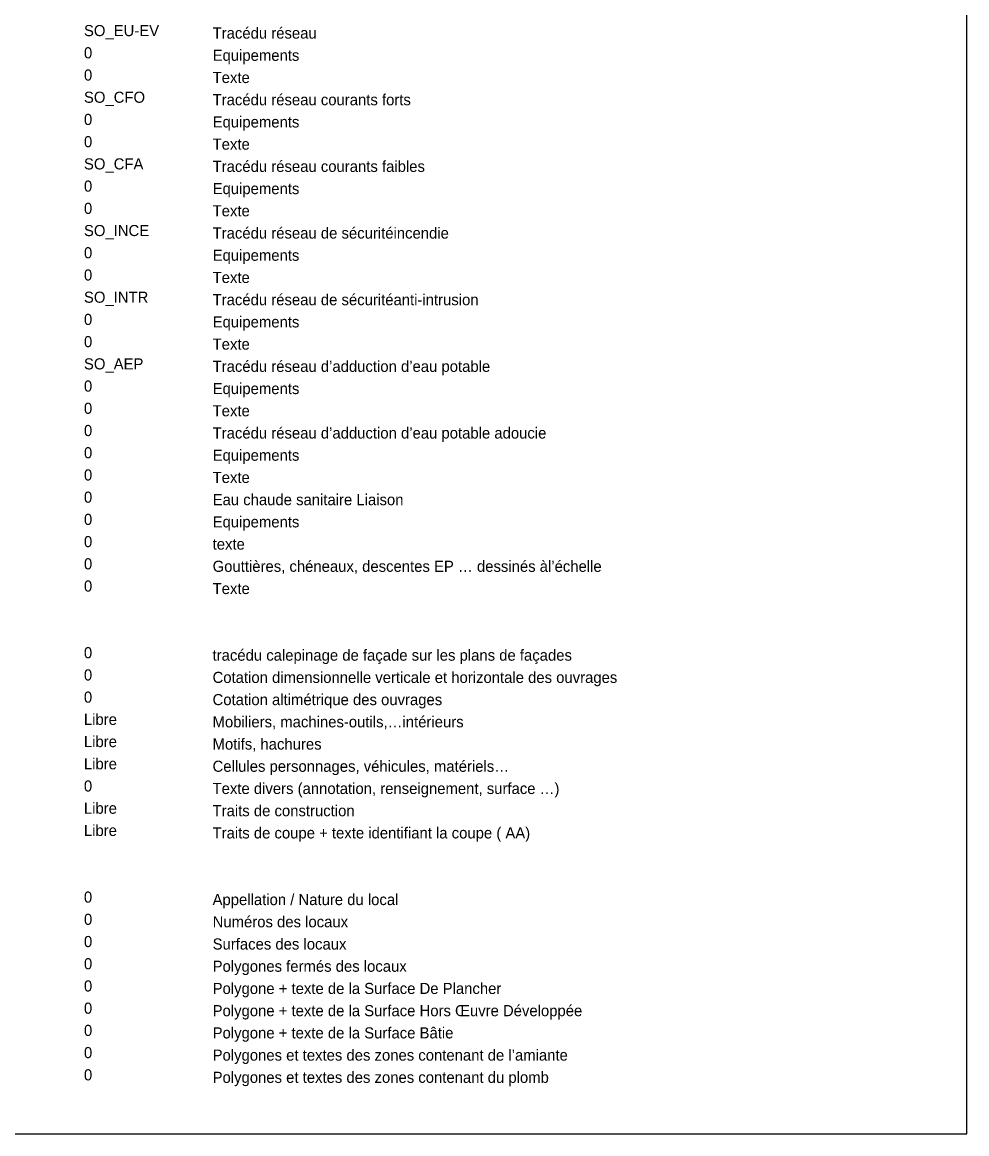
# Model space of a CAD drawing. Extents: x -60 to 214, y -380 to -21.
# Drawn here: x 166.2 to 208.7, y -120.9 to -70.9 of the extents above; entities that cross this region are included whole.
import ezdxf

# ---------------------------------------------------------------- set-up
doc = ezdxf.new("R2010")
doc.units = 0
for name, color, linetype in [('BAT_DH_CALEPINAGE_FACADE', 7, 'Continuous'), ('BAT_DH_COTATION', 7, 'Continuous'), ('BAT_DH_COTATION_NGF', 7, 'Continuous'), ('BAT_DH_EQUIP INTERIEUR', 7, 'Continuous'), ('BAT_DH_HACHURE-MOTIF', 7, 'Continuous'), ('BAT_DH_PERSONNAGE_VEHICULES', 7, 'Continuous'), ('BAT_DH_TEXTE', 7, 'Continuous'), ('BAT_DH_TRAIT CONSTRUCTION', 7, 'Continuous'), ('BAT_DH_TRAIT DE COUPE', 7, 'Continuous'), ('BAT_SID_AMIANTE_POLYLIGNE_TEXTE', 7, 'Continuous'), ('BAT_SID_LOCAL_NOM', 7, 'Continuous'), ('BAT_SID_LOCAL_NUMERO', 7, 'Continuous'), ('BAT_SID_LOCAL_POLYLIGNE', 7, 'Continuous'), ('BAT_SID_LOCAL_SURFACE', 7, 'Continuous'), ('BAT_SID_PLOMB_POLYLIGNE_TEXTE', 7, 'Continuous'), ('BAT_SID_SBAT_POLYLIGNE_TEXTE', 7, 'Continuous'), ('BAT_SID_SDP_POLYLIGNE_TEXTE', 7, 'Continuous'), ('BAT_SID_SHOD_POLYLIGNE_TEXTE', 7, 'Continuous'), ('Default', 7, 'Continuous'), ('SO_AEP_AD_EQUIP', 7, 'Continuous'), ('SO_AEP_AD_LIAISON', 7, 'Continuous'), ('SO_AEP_AD_TEXTE', 7, 'Continuous'), ('SO_AEP_EQUIP', 7, 'Continuous'), ('SO_AEP_LIAISON', 7, 'Continuous'), ('SO_AEP_TEXTE', 7, 'Continuous'), ('SO_ANTI_INTRUSION_EQUIP', 7, 'Continuous'), ('SO_ANTI_INTRUSION_LIAISON', 7, 'Continuous'), ('SO_ANTI_INTRUSION_TEXTE', 7, 'Continuous'), ('SO_ECS_EQUIP', 7, 'Continuous'), ('SO_ECS_LIAISON', 7, 'Continuous'), ('SO_ECS_TEXTE', 7, 'Continuous'), ('SO_ELEC_C_FAIBLES_EQUIP', 7, 'Continuous'), ('SO_ELEC_C_FAIBLES_LIAISON', 7, 'Continuous'), ('SO_ELEC_C_FAIBLES_TEXTE', 7, 'Continuous'), ('SO_ELEC_C_FORTS_EQUIP', 7, 'Continuous'), ('SO_ELEC_C_FORTS_LIAISON', 7, 'Continuous'), ('SO_ELEC_C_FORTS_TEXTE', 7, 'Continuous'), ('SO_EP_EQUIP', 7, 'Continuous'), ('SO_EP_TEXTE', 7, 'Continuous'), ('SO_EU_EV_EQUIP', 7, 'Continuous'), ('SO_EU_EV_LIAISON', 7, 'Continuous'), ('SO_EU_EV_TEXTE', 7, 'Continuous'), ('SO_SECU_INCENDIE_EQUIP', 7, 'Continuous'), ('SO_SECU_INCENDIE_LIAISON', 7, 'Continuous'), ('SO_SECU_INCENDIE_TEXTE', 7, 'Continuous')]:
    doc.layers.add(name, color=color, linetype=linetype)

msp = doc.modelspace()

# ---------------------------------------------------------------- linework, layer by layer
at = {"layer": 'Default'}
msp.add_lwpolyline([(208.701, -25.727), (123.7, -25.727), (123.7, -120.902), (208.701, -120.902)], close=True, dxfattribs=at)

# ---------------------------------------------------------------- texts
at = {"layer": 'BAT_DH_CALEPINAGE_FACADE'}
for s, p in [('0 ', (168.976, -99.499)), ('tracédu calepinage de façade sur les plans de façades ', (174.765, -99.61))]:
    msp.add_text(s, height=0.5, dxfattribs=at).set_placement(p)
at = {"layer": 'BAT_DH_COTATION'}
for s, p in [('0 ', (168.976, -100.499)), ('Cotation dimensionnelle verticale et horizontale des ouvrages ', (174.765, -100.61))]:
    msp.add_text(s, height=0.5, dxfattribs=at).set_placement(p)
at = {"layer": 'BAT_DH_COTATION_NGF'}
for s, p in [('0 ', (168.976, -101.499)), ('Cotation altimétrique des ouvrages ', (174.765, -101.61))]:
    msp.add_text(s, height=0.5, dxfattribs=at).set_placement(p)
at = {"layer": 'BAT_DH_EQUIP INTERIEUR'}
for s, p in [('Libre ', (168.976, -102.499)), ('Mobiliers, machines-outils,…intérieurs ', (174.765, -102.61))]:
    msp.add_text(s, height=0.5, dxfattribs=at).set_placement(p)
at = {"layer": 'BAT_DH_HACHURE-MOTIF'}
for s, p in [('Libre ', (168.976, -103.499)), ('Motifs, hachures ', (174.765, -103.61))]:
    msp.add_text(s, height=0.5, dxfattribs=at).set_placement(p)
at = {"layer": 'BAT_DH_PERSONNAGE_VEHICULES'}
for s, p in [('Libre ', (168.976, -104.499)), ('Cellules personnages, véhicules, matériels…', (174.765, -104.61))]:
    msp.add_text(s, height=0.5, dxfattribs=at).set_placement(p)
at = {"layer": 'BAT_DH_TEXTE'}
for s, p in [('0 ', (168.976, -105.499)), ('Texte divers (annotation, renseignement, surface …)  ', (174.765, -105.61))]:
    msp.add_text(s, height=0.5, dxfattribs=at).set_placement(p)
at = {"layer": 'BAT_DH_TRAIT CONSTRUCTION'}
for s, p in [('Libre ', (168.976, -106.499)), ('Traits de construction  ', (174.765, -106.61))]:
    msp.add_text(s, height=0.5, dxfattribs=at).set_placement(p)
at = {"layer": 'BAT_DH_TRAIT DE COUPE'}
for s, p in [('Libre ', (168.976, -107.499)), ('Traits de coupe + texte identifiant la coupe ( AA) ', (174.765, -107.61))]:
    msp.add_text(s, height=0.5, dxfattribs=at).set_placement(p)
at = {"layer": 'BAT_SID_AMIANTE_POLYLIGNE_TEXTE'}
for s, p in [('0 ', (168.978, -117.499)), ('Polygones et textes des zones contenant de l’amiante ', (174.768, -117.61))]:
    msp.add_text(s, height=0.5, dxfattribs=at).set_placement(p)
at = {"layer": 'BAT_SID_LOCAL_NOM'}
for s, p in [('0 ', (168.976, -110.499)), ('Appellation / Nature du local ', (174.765, -110.61))]:
    msp.add_text(s, height=0.5, dxfattribs=at).set_placement(p)
at = {"layer": 'BAT_SID_LOCAL_NUMERO'}
for s, p in [('0 ', (168.978, -111.499)), ('Numéros des locaux ', (174.768, -111.61))]:
    msp.add_text(s, height=0.5, dxfattribs=at).set_placement(p)
at = {"layer": 'BAT_SID_LOCAL_POLYLIGNE'}
for s, p in [('0 ', (168.978, -113.499)), ('Polygones fermés des locaux ', (174.768, -113.61))]:
    msp.add_text(s, height=0.5, dxfattribs=at).set_placement(p)
at = {"layer": 'BAT_SID_LOCAL_SURFACE'}
for s, p in [('0 ', (168.978, -112.499)), ('Surfaces des locaux ', (174.768, -112.61))]:
    msp.add_text(s, height=0.5, dxfattribs=at).set_placement(p)
at = {"layer": 'BAT_SID_PLOMB_POLYLIGNE_TEXTE'}
for s, p in [('0 ', (168.978, -118.499)), ('Polygones et textes des zones contenant du plomb ', (174.768, -118.61))]:
    msp.add_text(s, height=0.5, dxfattribs=at).set_placement(p)
at = {"layer": 'BAT_SID_SBAT_POLYLIGNE_TEXTE'}
for s, p in [('0 ', (168.978, -116.499)), ('Polygone + texte de la Surface Bâtie ', (174.768, -116.61))]:
    msp.add_text(s, height=0.5, dxfattribs=at).set_placement(p)
at = {"layer": 'BAT_SID_SDP_POLYLIGNE_TEXTE'}
for s, p in [('0 ', (168.978, -114.499)), ('Polygone + texte de la Surface De Plancher ', (174.768, -114.61))]:
    msp.add_text(s, height=0.5, dxfattribs=at).set_placement(p)
at = {"layer": 'BAT_SID_SHOD_POLYLIGNE_TEXTE'}
for s, p in [('0 ', (168.978, -115.499)), ('Polygone + texte de la Surface Hors Œuvre Développée ', (174.768, -115.61))]:
    msp.add_text(s, height=0.5, dxfattribs=at).set_placement(p)
at = {"layer": 'SO_AEP_AD_EQUIP'}
for s, p in [('0 ', (168.978, -90.499)), ('Equipements ', (174.768, -90.61))]:
    msp.add_text(s, height=0.5, dxfattribs=at).set_placement(p)
at = {"layer": 'SO_AEP_AD_LIAISON'}
for s, p in [('0 ', (168.978, -89.499)), ('Tracédu réseau d’adduction d’eau potable adoucie ', (174.768, -89.61))]:
    msp.add_text(s, height=0.5, dxfattribs=at).set_placement(p)
at = {"layer": 'SO_AEP_AD_TEXTE'}
for s, p in [('0 ', (168.978, -91.499)), ('Texte ', (174.768, -91.61))]:
    msp.add_text(s, height=0.5, dxfattribs=at).set_placement(p)
at = {"layer": 'SO_AEP_EQUIP'}
for s, p in [('0 ', (168.978, -87.499)), ('Equipements ', (174.768, -87.61))]:
    msp.add_text(s, height=0.5, dxfattribs=at).set_placement(p)
at = {"layer": 'SO_AEP_LIAISON'}
for s, p in [('SO_AEP ', (168.978, -86.499)), ('Tracédu réseau d’adduction d’eau potable ', (174.768, -86.61))]:
    msp.add_text(s, height=0.5, dxfattribs=at).set_placement(p)
at = {"layer": 'SO_AEP_TEXTE'}
for s, p in [('0 ', (168.978, -88.499)), ('Texte ', (174.768, -88.61))]:
    msp.add_text(s, height=0.5, dxfattribs=at).set_placement(p)
at = {"layer": 'SO_ANTI_INTRUSION_EQUIP'}
for s, p in [('0 ', (168.978, -84.499)), ('Equipements ', (174.768, -84.61))]:
    msp.add_text(s, height=0.5, dxfattribs=at).set_placement(p)
at = {"layer": 'SO_ANTI_INTRUSION_LIAISON'}
for s, p in [('SO_INTR ', (168.978, -83.499)), ('Tracédu réseau de sécuritéanti-intrusion ', (174.768, -83.61))]:
    msp.add_text(s, height=0.5, dxfattribs=at).set_placement(p)
at = {"layer": 'SO_ANTI_INTRUSION_TEXTE'}
for s, p in [('0 ', (168.978, -85.499)), ('Texte ', (174.768, -85.61))]:
    msp.add_text(s, height=0.5, dxfattribs=at).set_placement(p)
at = {"layer": 'SO_ECS_EQUIP'}
for s, p in [('0 ', (168.978, -93.499)), ('Equipements ', (174.768, -93.61))]:
    msp.add_text(s, height=0.5, dxfattribs=at).set_placement(p)
at = {"layer": 'SO_ECS_LIAISON'}
for s, p in [('0 ', (168.978, -92.499)), ('Eau chaude sanitaire Liaison ', (174.768, -92.61))]:
    msp.add_text(s, height=0.5, dxfattribs=at).set_placement(p)
at = {"layer": 'SO_ECS_TEXTE'}
for s, p in [('0 ', (168.978, -94.499)), ('texte ', (174.768, -94.61))]:
    msp.add_text(s, height=0.5, dxfattribs=at).set_placement(p)
at = {"layer": 'SO_ELEC_C_FAIBLES_EQUIP'}
for s, p in [('0 ', (168.978, -78.499)), ('Equipements ', (174.768, -78.61))]:
    msp.add_text(s, height=0.5, dxfattribs=at).set_placement(p)
at = {"layer": 'SO_ELEC_C_FAIBLES_LIAISON'}
for s, p in [('SO_CFA ', (168.978, -77.499)), ('Tracédu réseau courants faibles ', (174.768, -77.61))]:
    msp.add_text(s, height=0.5, dxfattribs=at).set_placement(p)
at = {"layer": 'SO_ELEC_C_FAIBLES_TEXTE'}
for s, p in [('0 ', (168.978, -79.499)), ('Texte ', (174.768, -79.61))]:
    msp.add_text(s, height=0.5, dxfattribs=at).set_placement(p)
at = {"layer": 'SO_ELEC_C_FORTS_EQUIP'}
for s, p in [('0 ', (168.978, -75.499)), ('Equipements ', (174.768, -75.61))]:
    msp.add_text(s, height=0.5, dxfattribs=at).set_placement(p)
at = {"layer": 'SO_ELEC_C_FORTS_LIAISON'}
for s, p in [('SO_CFO ', (168.978, -74.499)), ('Tracédu réseau courants forts ', (174.768, -74.61))]:
    msp.add_text(s, height=0.5, dxfattribs=at).set_placement(p)
at = {"layer": 'SO_ELEC_C_FORTS_TEXTE'}
for s, p in [('0 ', (168.978, -76.499)), ('Texte ', (174.768, -76.61))]:
    msp.add_text(s, height=0.5, dxfattribs=at).set_placement(p)
at = {"layer": 'SO_EP_EQUIP'}
for s, p in [('0 ', (168.978, -95.499)), ('Gouttières, chéneaux, descentes EP … dessinés àl’échelle ', (174.768, -95.61))]:
    msp.add_text(s, height=0.5, dxfattribs=at).set_placement(p)
at = {"layer": 'SO_EP_TEXTE'}
for s, p in [('0 ', (168.978, -96.499)), ('Texte ', (174.768, -96.61))]:
    msp.add_text(s, height=0.5, dxfattribs=at).set_placement(p)
at = {"layer": 'SO_EU_EV_EQUIP'}
for s, p in [('0 ', (168.978, -72.499)), ('Equipements ', (174.768, -72.61))]:
    msp.add_text(s, height=0.5, dxfattribs=at).set_placement(p)
at = {"layer": 'SO_EU_EV_LIAISON'}
for s, p in [('SO_EU-EV ', (168.978, -71.499)), ('Tracédu réseau ', (174.768, -71.61))]:
    msp.add_text(s, height=0.5, dxfattribs=at).set_placement(p)
at = {"layer": 'SO_EU_EV_TEXTE'}
for s, p in [('0 ', (168.978, -73.499)), ('Texte ', (174.768, -73.61))]:
    msp.add_text(s, height=0.5, dxfattribs=at).set_placement(p)
at = {"layer": 'SO_SECU_INCENDIE_EQUIP'}
for s, p in [('0 ', (168.978, -81.499)), ('Equipements ', (174.768, -81.61))]:
    msp.add_text(s, height=0.5, dxfattribs=at).set_placement(p)
at = {"layer": 'SO_SECU_INCENDIE_LIAISON'}
for s, p in [('SO_INCE ', (168.978, -80.499)), ('Tracédu réseau de sécuritéincendie ', (174.768, -80.61))]:
    msp.add_text(s, height=0.5, dxfattribs=at).set_placement(p)
at = {"layer": 'SO_SECU_INCENDIE_TEXTE'}
for s, p in [('0 ', (168.978, -82.499)), ('Texte ', (174.768, -82.61))]:
    msp.add_text(s, height=0.5, dxfattribs=at).set_placement(p)

doc.saveas('drawing.dxf')
